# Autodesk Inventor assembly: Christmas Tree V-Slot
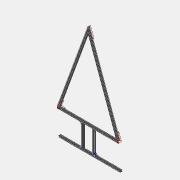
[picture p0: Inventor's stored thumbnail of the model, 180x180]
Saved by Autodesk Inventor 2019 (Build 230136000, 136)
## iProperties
Created: 2025-12
Part Number: Christmas Tree V-Slot
Document SubType Name: Assembly
Designer: sab
Author: sab
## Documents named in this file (10)
- C:\Users\sab\Documents\Inventor\Maker Store Parts\Other Stuff\Christmas Tree V-Slot\Christmas Tree V-Slot.iam
- C:\Users\sab\Documents\Inventor\Maker Store Parts\Other Stuff\Christmas Tree V-Slot\LR-2020-S-1000 cut for christmas tree.ipt
- C:\Users\sab\Documents\Inventor\Maker Store Parts\Other Stuff\Christmas Tree V-Slot\LR-2020-S-684.04.ipt
- C:\Users\sab\Documents\Inventor\Maker Store Parts\Other Stuff\Christmas Tree V-Slot\LR-2020-S-250.ipt
- C:\Users\sab\Documents\Inventor\Maker Store Parts\BRAC-90CAST.ipt
- C:\Users\sab\Documents\Inventor\Content Center Files\R2019\en-US\ISO 7380-1\ISO 7380-1 - M5 x 12.ipt
- C:\Users\sab\Documents\Inventor\Maker Store Parts\Other Stuff\Christmas Tree V-Slot\Christmas Tree Corner Bracket Type 2.ipt
- C:\Users\sab\Documents\Inventor\Maker Store Parts\Other Stuff\Christmas Tree V-Slot\Christmas Tree Corner Bracket Type 1 v2.ipt
- C:\Users\sab\Documents\Inventor\Maker Store Parts\Other Stuff\Christmas Tree V-Slot\Christmas Tree Corner Bracket Type 1 Right v2.ipt
- C:\Users\sab\Documents\Inventor\Maker Store Parts\Other Stuff\Christmas Tree V-Slot\LR-2020-S-641.47.ipt
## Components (14 placed, 9 different names)
1. LR-2020-S-641.47:1 — Flush:1, Flush:2, Mate:5, Mate:7, Mate:8, Mate:9, Flush:3, Flush:4, Flush:5, Flush:6, Flush:8, Mate:12, Mate:18, Mate:19, Flush:15, Mate:22, Mate:23, Flush:19, Mate:24
2. LR-2020-S-1000 cut for christmas tree:1 — Flush:2, Mate:4, Mate:5, Flush:18, Flush:20
3. LR-2020-S-1000 cut for christmas tree:2 — Flush:1, Mate:4, Mate:7, Mate:21, Flush:17
4. LR-2020-S-250:1 — Mate:8, Flush:4, Flush:6, Mate:10, Flush:7, Mate:11, Mate:15, Flush:9
5. LR-2020-S-250:2 — Mate:9, Flush:3, Flush:5, Mate:16, Mate:17
6. LR-2020-S-684.04:2 — Mate:10, Flush:7, Flush:8, Mate:13, Mate:14
7. BRAC-90CAST:1 — Mate:11, Mate:18, Flush:9, Flush:10, Flush:11
8. BRAC-90CAST:2 — Mate:14, Mate:15, Flush:11, Flush:12
9. BRAC-90CAST:3 — Mate:12, Mate:17, Flush:10
10. BRAC-90CAST:4 — Mate:13, Mate:16, Flush:12
11. ISO 7380-1 M5 x 12:1 — Insert:1
12. Christmas Tree Corner Bracket Type 1 v2:1 — Mate:19, Flush:15, Mate:22, Insert:1
13. Christmas Tree Corner Bracket Type 1 Right v2:1 — Mate:23, Flush:19, Mate:24, Flush:20
14. Christmas Tree Corner Bracket Type 2:1 — Mate:21, Flush:17, Flush:18
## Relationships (37: Mate 19, Flush 17, Insert 1)
- Flush:1: LR-2020-S-641.47:1 ↔ LR-2020-S-1000 cut for christmas tree:2
- Flush:2: LR-2020-S-641.47:1 ↔ LR-2020-S-1000 cut for christmas tree:1
- Mate:4: LR-2020-S-1000 cut for christmas tree:1 ↔ LR-2020-S-1000 cut for christmas tree:2
- Mate:5: LR-2020-S-641.47:1 ↔ LR-2020-S-1000 cut for christmas tree:1
- Mate:7: LR-2020-S-641.47:1 ↔ LR-2020-S-1000 cut for christmas tree:2
- Mate:8: LR-2020-S-641.47:1 ↔ LR-2020-S-250:1
- Mate:9: LR-2020-S-641.47:1 ↔ LR-2020-S-250:2
- Flush:3: LR-2020-S-641.47:1 ↔ LR-2020-S-250:2
- Flush:4: LR-2020-S-641.47:1 ↔ LR-2020-S-250:1
- Flush:5: LR-2020-S-641.47:1 ↔ LR-2020-S-250:2
- Flush:6: LR-2020-S-641.47:1 ↔ LR-2020-S-250:1
- Mate:10: LR-2020-S-250:1 ↔ LR-2020-S-684.04:2
- Flush:7: LR-2020-S-250:1 ↔ LR-2020-S-684.04:2
- Flush:8: LR-2020-S-641.47:1 ↔ LR-2020-S-684.04:2
- Mate:11: LR-2020-S-250:1 ↔ BRAC-90CAST:1
- Mate:12: LR-2020-S-641.47:1 ↔ BRAC-90CAST:3
- Mate:13: LR-2020-S-684.04:2 ↔ BRAC-90CAST:4
- Mate:14: LR-2020-S-684.04:2 ↔ BRAC-90CAST:2
- Mate:15: LR-2020-S-250:1 ↔ BRAC-90CAST:2
- Mate:16: LR-2020-S-250:2 ↔ BRAC-90CAST:4
- Mate:17: LR-2020-S-250:2 ↔ BRAC-90CAST:3
- Mate:18: LR-2020-S-641.47:1 ↔ BRAC-90CAST:1
- Flush:9: LR-2020-S-250:1 ↔ BRAC-90CAST:1
- Flush:10: BRAC-90CAST:1 ↔ BRAC-90CAST:3
- Flush:11: BRAC-90CAST:1 ↔ BRAC-90CAST:2
- Flush:12: BRAC-90CAST:2 ↔ BRAC-90CAST:4
- Mate:19: LR-2020-S-641.47:1 ↔ Christmas Tree Corner Bracket Type 1 v2:1
- Flush:15: LR-2020-S-641.47:1 ↔ Christmas Tree Corner Bracket Type 1 v2:1
- Mate:21: LR-2020-S-1000 cut for christmas tree:2 ↔ Christmas Tree Corner Bracket Type 2:1
- Flush:17: LR-2020-S-1000 cut for christmas tree:2 ↔ Christmas Tree Corner Bracket Type 2:1
- Flush:18: LR-2020-S-1000 cut for christmas tree:1 ↔ Christmas Tree Corner Bracket Type 2:1
- Mate:22: LR-2020-S-641.47:1 ↔ Christmas Tree Corner Bracket Type 1 v2:1
- Mate:23: LR-2020-S-641.47:1 ↔ Christmas Tree Corner Bracket Type 1 Right v2:1
- Flush:19: LR-2020-S-641.47:1 ↔ Christmas Tree Corner Bracket Type 1 Right v2:1
- Mate:24: LR-2020-S-641.47:1 ↔ Christmas Tree Corner Bracket Type 1 Right v2:1
- Flush:20: LR-2020-S-1000 cut for christmas tree:1 ↔ Christmas Tree Corner Bracket Type 1 Right v2:1
- Insert:1: ISO 7380-1 M5 x 12:1 ↔ Christmas Tree Corner Bracket Type 1 v2:1
